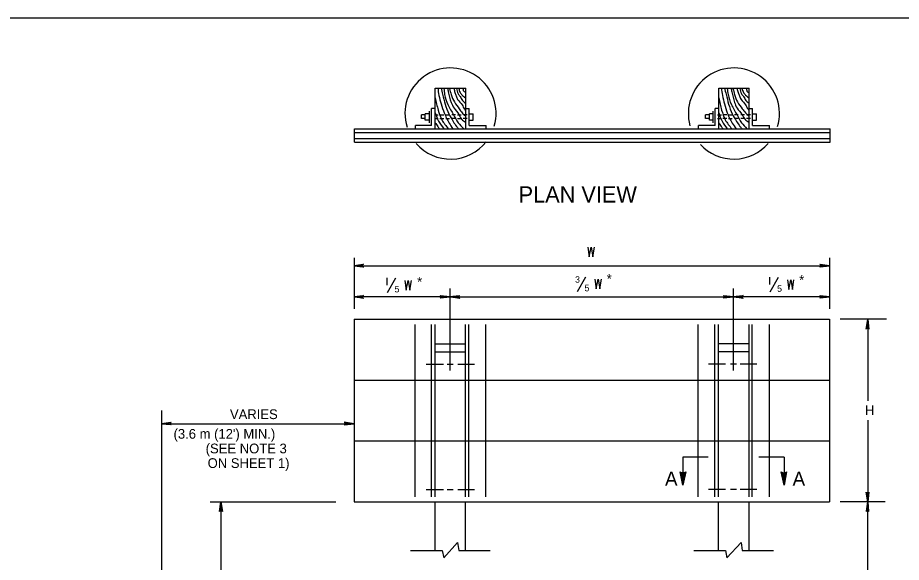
# Model space of a CAD drawing. Extents: x -1958 to 628, y -879 to 309.
# Drawn here: x -737.1 to -465.1, y -467.1 to -299.6 of the extents above; entities that cross this region are included whole.
import ezdxf

# ---------------------------------------------------------------- set-up
doc = ezdxf.new("R2010")
doc.units = 0
for name, color, linetype in [('1', 7, 'Continuous'), ('2', 7, 'Continuous'), ('3', 7, 'Continuous')]:
    doc.layers.add(name, color=color, linetype=linetype)

msp = doc.modelspace()

# ---------------------------------------------------------------- linework, layer by layer
at = {"layer": '1'}
msp.add_line((-1077.39, -299.56), (-291.39, -299.56), dxfattribs=at)
at = {"layer": '2'}
for p, q in [((-608.5, -321.24), (-599.13, -321.24)), ((-521.25, -321.24), (-511.88, -321.24)), ((-608.5, -327.49), (-609.63, -327.49)), ((-599.13, -327.49), (-598.13, -327.49)), ((-521.25, -327.49), (-522.38, -327.49)), ((-511.88, -327.49), (-510.88, -327.49)), ((-633.38, -333.74), (-487, -333.74)), ((-609.63, -332.74), (-614.63, -332.74)), ((-598.13, -332.74), (-592.88, -332.74)), ((-522.38, -332.74), (-527.5, -332.74)), ((-510.88, -332.74), (-505.63, -332.74)), ((-633.38, -334.86), (-487, -334.86)), ((-633.38, -336.74), (-487, -336.74)), ((-633.38, -337.86), (-487, -337.86)), ((-633.53, -392.36), (-487.15, -392.36)), ((-633.53, -392.36), (-633.53, -448.48)), ((-614.78, -393.98), (-614.78, -446.98)), ((-609.78, -393.98), (-609.78, -446.98)), ((-608.65, -393.98), (-608.65, -446.98)), ((-599.28, -393.98), (-599.28, -446.98)), ((-598.28, -393.98), (-598.28, -446.98)), ((-593.03, -393.98), (-593.03, -446.98)), ((-527.65, -393.98), (-527.65, -446.98)), ((-522.53, -393.98), (-522.53, -446.98)), ((-521.4, -393.98), (-521.4, -446.98)), ((-512.03, -393.98), (-512.03, -446.98)), ((-511.03, -393.98), (-511.03, -446.98)), ((-505.78, -393.98), (-505.78, -446.98)), ((-487.15, -392.36), (-487.15, -448.48)), ((-608.65, -399.86), (-599.28, -399.86)), ((-608.65, -402.36), (-599.28, -402.36)), ((-512.03, -399.86), (-521.4, -399.86)), ((-512.03, -402.36), (-521.4, -402.36)), ((-633.53, -411.11), (-487.15, -411.11)), ((-633.53, -429.73), (-487.15, -429.73)), ((-633.53, -448.48), (-487.15, -448.48)), ((-608.65, -448.48), (-608.65, -463.48)), ((-599.28, -448.48), (-599.28, -463.48)), ((-521.4, -448.48), (-521.4, -463.48)), ((-512.03, -448.48), (-512.03, -463.48)), ((-605.9, -465.73), (-601.65, -460.98)), ((-601.65, -460.98), (-601.28, -463.48)), ((-518.78, -465.73), (-514.4, -460.98)), ((-514.4, -460.98), (-514.03, -463.48)), ((-616.15, -463.48), (-606.4, -463.48)), ((-606.4, -463.48), (-605.9, -465.73)), ((-601.28, -463.48), (-591.65, -463.48)), ((-528.9, -463.48), (-519.15, -463.48)), ((-519.15, -463.48), (-518.78, -465.73)), ((-514.03, -463.48), (-504.4, -463.48))]:
    msp.add_line(p, q, dxfattribs=at)
at = {"layer": '3'}
for p, q in [((-608.5, -333.74), (-608.5, -321.24)), ((-599.13, -333.74), (-599.13, -321.24)), ((-521.25, -333.74), (-521.25, -321.24)), ((-511.88, -333.74), (-511.88, -321.24)), ((-611.63, -331.11), (-611.63, -329.11)), ((-610.25, -329.11), (-611.63, -329.11)), ((-610.25, -331.86), (-610.25, -328.36)), ((-609.63, -332.74), (-609.63, -327.49)), ((-598.13, -332.74), (-598.13, -327.49)), ((-598.13, -329.11), (-596.88, -329.11)), ((-596.88, -331.11), (-596.88, -329.11)), ((-524.13, -331.11), (-524.13, -329.11)), ((-523, -329.11), (-524.13, -329.11)), ((-523, -331.86), (-523, -328.36)), ((-522.38, -332.74), (-522.38, -327.49)), ((-510.88, -332.74), (-510.88, -327.49)), ((-510.88, -329.11), (-509.63, -329.11)), ((-509.63, -331.11), (-509.63, -329.11)), ((-612.75, -330.61), (-612.75, -329.49)), ((-611.63, -329.49), (-612.75, -329.49)), ((-611.63, -330.61), (-612.75, -330.61)), ((-610.25, -331.11), (-611.63, -331.11)), ((-608.75, -329.49), (-607.63, -329.49)), ((-608.75, -330.61), (-607.63, -330.61)), ((-607.13, -329.49), (-605.88, -329.49)), ((-607.13, -330.61), (-605.88, -330.61)), ((-605.25, -329.49), (-604.13, -329.49)), ((-605.25, -330.61), (-604.13, -330.61)), ((-602.25, -329.49), (-603.38, -329.49)), ((-602.25, -330.61), (-603.38, -330.61)), ((-601.63, -329.49), (-600.5, -329.49)), ((-601.63, -330.61), (-600.5, -330.61)), ((-598.75, -329.49), (-599.88, -329.49)), ((-598.75, -330.61), (-599.88, -330.61)), ((-598.13, -331.11), (-596.88, -331.11)), ((-525.38, -330.61), (-525.38, -329.49)), ((-524.13, -329.49), (-525.38, -329.49)), ((-524.13, -330.61), (-525.38, -330.61)), ((-523, -331.11), (-524.13, -331.11)), ((-521.63, -329.49), (-520.38, -329.49)), ((-521.63, -330.61), (-520.38, -330.61)), ((-518.75, -329.49), (-520, -329.49)), ((-518.75, -330.61), (-520, -330.61)), ((-518.25, -329.49), (-517.13, -329.49)), ((-518.25, -330.61), (-517.13, -330.61)), ((-515.25, -329.49), (-516.38, -329.49)), ((-515.25, -330.61), (-516.38, -330.61)), ((-513.38, -329.49), (-514.5, -329.49)), ((-513.38, -330.61), (-514.5, -330.61)), ((-511.5, -329.49), (-512.75, -329.49)), ((-511.5, -330.61), (-512.75, -330.61)), ((-510.88, -331.11), (-509.63, -331.11)), ((-633.38, -337.86), (-633.38, -333.74)), ((-614.63, -333.74), (-614.63, -332.74)), ((-592.88, -333.74), (-592.88, -332.74)), ((-527.5, -333.74), (-527.5, -332.74)), ((-505.63, -333.74), (-505.63, -332.74)), ((-487, -337.86), (-487, -333.74)), ((-633.53, -373.48), (-633.53, -389.11)), ((-487.15, -373.48), (-487.15, -389.11)), ((-633.53, -375.86), (-487.15, -375.86)), ((-604.03, -382.86), (-604.03, -408.11)), ((-516.78, -382.86), (-516.78, -408.11)), ((-604.03, -385.48), (-633.53, -385.48)), ((-604.03, -385.48), (-516.78, -385.48)), ((-487.15, -385.48), (-516.78, -385.48)), ((-469.66, -392.36), (-483.9, -392.36)), ((-475.4, -392.36), (-475.4, -417.4)), ((-611.28, -406.11), (-606.03, -406.11)), ((-604.9, -406.11), (-603.03, -406.11)), ((-601.53, -406.11), (-596.4, -406.11)), ((-519.15, -406.11), (-524.4, -406.11)), ((-515.78, -406.11), (-517.65, -406.11)), ((-509.53, -406.11), (-514.65, -406.11)), ((-692.78, -420.36), (-692.78, -554.59)), ((-475.4, -423.42), (-475.4, -448.48)), ((-692.78, -424.48), (-633.53, -424.48)), ((-532.28, -434.73), (-532.28, -443.36)), ((-524.53, -434.73), (-532.28, -434.73)), ((-501.15, -434.73), (-508.9, -434.73)), ((-501.15, -434.73), (-501.15, -443.36)), ((-611.28, -444.73), (-606.03, -444.73)), ((-604.9, -444.73), (-603.03, -444.73)), ((-601.53, -444.73), (-596.4, -444.73)), ((-519.15, -444.73), (-524.4, -444.73)), ((-515.78, -444.73), (-517.65, -444.73)), ((-509.53, -444.73), (-514.65, -444.73)), ((-677.82, -448.48), (-639.15, -448.48)), ((-674.48, -448.48), (-674.48, -557.43)), ((-470.04, -448.48), (-483.9, -448.48)), ((-475.4, -496.98), (-475.4, -448.48))]:
    msp.add_line(p, q, dxfattribs=at)
for points in [[(-561.52, -370.12), (-561.1, -373.12), (-560.53, -370.12), (-559.99, -373.12), (-559.51, -370.12)], [(-630.78, -376.23), (-630.9, -376.11), (-633.53, -375.86), (-630.78, -376.23), (-630.65, -376.36), (-633.53, -375.86), (-630.9, -375.73), (-630.78, -375.48), (-633.53, -375.86), (-630.65, -375.36), (-630.78, -375.48)], [(-490.03, -375.48), (-489.9, -375.73), (-487.15, -375.86), (-490.03, -375.48), (-490.15, -375.36), (-487.15, -375.86), (-489.9, -375.98), (-490.03, -376.23), (-487.15, -375.86), (-490.15, -376.36), (-490.03, -376.23)], [(-623.34, -381.85), (-623.34, -379.61)], [(-623.22, -384.12), (-620.67, -379.61)], [(-617.88, -380.37), (-617.46, -383.37), (-616.89, -380.37), (-616.35, -383.37), (-615.88, -380.37)], [(-564.75, -383.77), (-562.2, -379.25)], [(-559.41, -380.01), (-558.98, -383.01), (-558.42, -380.01), (-557.87, -383.01), (-557.4, -380.01)], [(-505.57, -381.67), (-505.57, -379.43)], [(-505.46, -383.94), (-502.9, -379.43)], [(-500.12, -380.19), (-499.69, -383.19), (-499.12, -380.19), (-498.58, -383.19), (-498.11, -380.19)], [(-630.78, -385.73), (-630.9, -385.73), (-633.53, -385.48), (-630.78, -385.73), (-630.65, -385.98), (-633.53, -385.48), (-630.9, -385.36), (-630.78, -385.11), (-633.53, -385.48), (-630.65, -384.98), (-630.78, -385.11)], [(-606.9, -385.11), (-606.78, -385.36), (-604.03, -385.48), (-606.9, -385.11), (-607.03, -384.98), (-604.03, -385.48), (-606.78, -385.61), (-606.9, -385.73), (-604.03, -385.48), (-607.03, -385.86), (-606.9, -385.73)], [(-601.15, -385.73), (-601.28, -385.73), (-604.03, -385.48), (-601.15, -385.73), (-601.03, -385.98), (-604.03, -385.48), (-601.28, -385.36), (-601.15, -385.11), (-604.03, -385.48), (-601.03, -384.98), (-601.15, -385.11)], [(-519.65, -385.11), (-519.53, -385.36), (-516.78, -385.48), (-519.65, -385.11), (-519.78, -384.98), (-516.78, -385.48), (-519.53, -385.61), (-519.65, -385.73), (-516.78, -385.48), (-519.78, -385.86), (-519.65, -385.73)], [(-513.9, -385.73), (-514.03, -385.73), (-516.78, -385.48), (-513.9, -385.73), (-513.78, -385.98), (-516.78, -385.48), (-514.03, -385.36), (-513.9, -385.11), (-516.78, -385.48), (-513.78, -384.98), (-513.9, -385.11)], [(-490.03, -385.11), (-489.9, -385.36), (-487.15, -385.48), (-490.03, -385.11), (-490.15, -384.98), (-487.15, -385.48), (-489.9, -385.61), (-490.03, -385.73), (-487.15, -385.48), (-490.15, -385.86), (-490.03, -385.73)], [(-475.78, -395.23), (-475.53, -395.11), (-475.4, -392.36), (-475.78, -395.23), (-475.9, -395.36), (-475.4, -392.36), (-475.28, -395.11), (-475.15, -395.23), (-475.4, -392.36), (-475.03, -395.36), (-475.15, -395.23)], [(-689.9, -424.73), (-690.03, -424.61), (-692.78, -424.48), (-689.9, -424.73), (-689.78, -424.86), (-692.78, -424.48), (-690.03, -424.36), (-689.9, -424.11), (-692.78, -424.48), (-689.78, -423.98), (-689.9, -424.11)], [(-636.4, -424.73), (-636.28, -424.61), (-633.53, -424.48), (-636.4, -424.73), (-636.53, -424.86), (-633.53, -424.48), (-636.28, -424.36), (-636.4, -424.11), (-633.53, -424.48), (-636.53, -423.98), (-636.4, -424.11)], [(-531.65, -439.48), (-532.03, -439.61), (-532.28, -443.36), (-531.65, -439.48), (-531.4, -439.23), (-532.28, -443.36), (-532.53, -439.61), (-532.9, -439.48), (-532.28, -443.36), (-533.15, -439.23), (-532.9, -439.48)], [(-500.65, -439.48), (-500.9, -439.61), (-501.15, -443.36), (-500.65, -439.48), (-500.4, -439.23), (-501.15, -443.36), (-501.4, -439.61), (-501.78, -439.48), (-501.15, -443.36), (-502.03, -439.23), (-501.78, -439.48)], [(-475.15, -445.73), (-475.28, -445.73), (-475.4, -448.48), (-475.15, -445.73), (-475.03, -445.48), (-475.4, -448.48), (-475.53, -445.73), (-475.78, -445.73), (-475.4, -448.48), (-475.9, -445.48), (-475.78, -445.73)], [(-674.85, -451.36), (-674.6, -451.23), (-674.48, -448.48), (-674.85, -451.36), (-674.98, -451.48), (-674.48, -448.48), (-674.35, -451.23), (-674.1, -451.36), (-674.48, -448.48), (-673.98, -451.48), (-674.1, -451.36)], [(-475.15, -451.36), (-475.28, -451.23), (-475.4, -448.48), (-475.15, -451.36), (-475.03, -451.48), (-475.4, -448.48), (-475.53, -451.23), (-475.78, -451.36), (-475.4, -448.48), (-475.9, -451.48), (-475.78, -451.36)]]:
    msp.add_lwpolyline(points, dxfattribs=at)
for centre, start, end in [((-603.83, -329.05), 344.085, 197.2873), ((-516.6, -329.05), 343.3743, 195.5154), ((-603.83, -329.05), 221.3222, 321.6878), ((-516.6, -329.05), 222.6593, 319.137)]:
    msp.add_arc(centre, 14.02, start, end, dxfattribs=at)
for points in [[(-607.75, -321.24), (-607.38, -323.49), (-606.75, -326.11), (-605.75, -328.86), (-604.25, -331.99), (-603.13, -333.74)], [(-606.75, -321.24), (-606.25, -323.11), (-604.38, -329.11), (-603, -331.49), (-602, -332.99), (-601.38, -333.74)], [(-605.88, -321.36), (-605.63, -323.24), (-604.63, -326.24), (-602.88, -329.49), (-601.5, -331.86), (-599.75, -333.74)], [(-604.75, -321.24), (-604.5, -322.36), (-603.63, -325.61), (-602.75, -327.36), (-601.25, -329.36), (-600.38, -330.86), (-599.25, -331.74)], [(-604.13, -321.36), (-603.63, -323.24), (-602.63, -325.49), (-601.13, -327.61), (-600.25, -328.86), (-599.25, -329.74)], [(-602.75, -321.36), (-602.5, -322.61), (-602.13, -323.61), (-601.63, -324.74), (-600.25, -326.36), (-599.5, -327.74), (-599.25, -327.99)], [(-602, -321.36), (-601.5, -322.99), (-600.88, -323.86), (-600.13, -324.99), (-599.25, -325.86)], [(-601.25, -321.36), (-600.88, -322.61), (-600.25, -323.36), (-599.25, -324.24)], [(-600, -321.36), (-599.88, -321.99), (-599.63, -322.24), (-599.25, -322.61)], [(-520.5, -321.24), (-520.13, -323.49), (-519.5, -326.11), (-518.63, -328.86), (-517.13, -331.99), (-515.88, -333.74)], [(-519.5, -321.24), (-519, -323.11), (-517.13, -329.11), (-515.75, -331.49), (-514.75, -332.99), (-514.13, -333.74)], [(-518.63, -321.36), (-518.38, -323.24), (-517.38, -326.24), (-515.63, -329.49), (-514.25, -331.86), (-512.63, -333.74)], [(-517.5, -321.24), (-517.25, -322.36), (-516.38, -325.61), (-515.63, -327.36), (-514.13, -329.36), (-513.13, -330.86), (-512, -331.74)], [(-516.88, -321.36), (-516.38, -323.24), (-515.5, -325.49), (-514, -327.61), (-513, -328.86), (-512, -329.74)], [(-515.63, -321.36), (-515.25, -322.61), (-514.88, -323.61), (-514.38, -324.74), (-513, -326.36), (-512.25, -327.74), (-512, -327.99)], [(-514.75, -321.36), (-514.25, -322.99), (-513.63, -323.86), (-512.88, -324.99), (-512, -325.86)], [(-514.13, -321.36), (-513.63, -322.61), (-513, -323.36), (-512, -324.24)], [(-512.75, -321.36), (-512.63, -321.99), (-512.5, -322.24), (-512, -322.61)], [(-608.5, -324.24), (-607.63, -327.99), (-606.5, -330.99), (-604.5, -333.74)], [(-521.25, -324.24), (-520.38, -327.99), (-519.25, -330.99), (-517.25, -333.74)], [(-608.5, -328.86), (-607.5, -331.36), (-605.88, -333.74)], [(-521.25, -328.86), (-520.25, -331.36), (-518.63, -333.74)], [(-608.5, -331.86), (-607.75, -332.99), (-607.13, -333.86)], [(-521.25, -331.86), (-520.5, -332.99), (-519.88, -333.86)]]:
    msp.add_spline(points, degree=3, dxfattribs=at)

# ---------------------------------------------------------------- texts
at = {"layer": '2'}
for p in [(-614.11, -382.32), (-555.76, -381.4), (-496.49, -381.77)]:
    msp.add_text('*', height=3, dxfattribs=at).set_placement(p)
at = {"layer": '3'}
for s, height, p in [('PLAN VIEW', 5, (-582.86, -356.43)), ('3', 2, (-565.48, -381.1)), ('5', 2, (-621.05, -384.08)), ('5', 2, (-562.57, -383.73)), ('5', 2, (-503.28, -383.9)), ('H', 3, (-476.27, -421.83)), ('VARIES', 3, (-671.72, -423.05)), ("(3.6 m (12') MIN.)", 3, (-689.08, -429.09)), ('(SEE NOTE 3', 3, (-679.19, -433.59)), ('ON SHEET 1)', 3, (-678.58, -438.09)), ('A', 4.3, (-537.78, -443.52)), ('A', 4.3, (-498.52, -443.52))]:
    msp.add_text(s, height=height, dxfattribs=at).set_placement(p)

doc.saveas('drawing.dxf')
